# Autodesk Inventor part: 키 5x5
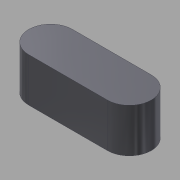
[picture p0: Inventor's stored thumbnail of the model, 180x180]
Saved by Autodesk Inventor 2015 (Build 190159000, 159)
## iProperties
Created: 2014-10
Part Number: 키 5x5
Document SubType Name: Modeling
Designer: KYOUNG IL JANG
Density: 7.86 g/cm^3
Mass: 2.54015 g
Surface Area: 2.9781 cm^2
Volume: 0.323175 cm^3
Material: 강철, 연강
Appearance: 강철 - 광택
Author: SeoGD™ [www.esajin.kr]
Revision Number: 1
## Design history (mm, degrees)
sketch "스케치1"
  geometry: L1 (-4.5, -2.5)-(4.5, -2.5); L2 (4.5, 2.5)-(-4.5, 2.5); A1 r 2.5 centre (4.5, 0) between (4.5, -2.5) and (4.5, 2.5); A2 r 2.5 centre (-4.5, 0) between (-4.5, 2.5) and (-4.5, -2.5); 2 further points
  constraints: 4 end point, 4 point on circle, 4 tangent, 2 centre point, 1 horizontal, 1 horizontal alignment, 1 midpoint, 1 parallel, 1 vertical alignment
  dimensions: "d0" = 5 distance between parallel lines of L1 L2; "d1" = 14 dimension on A1 A2
extrude "돌출1" new body sketch "스케치1" stored distance "d2" = 5; taper "d3" = 0 deg
node "솔리드1"
